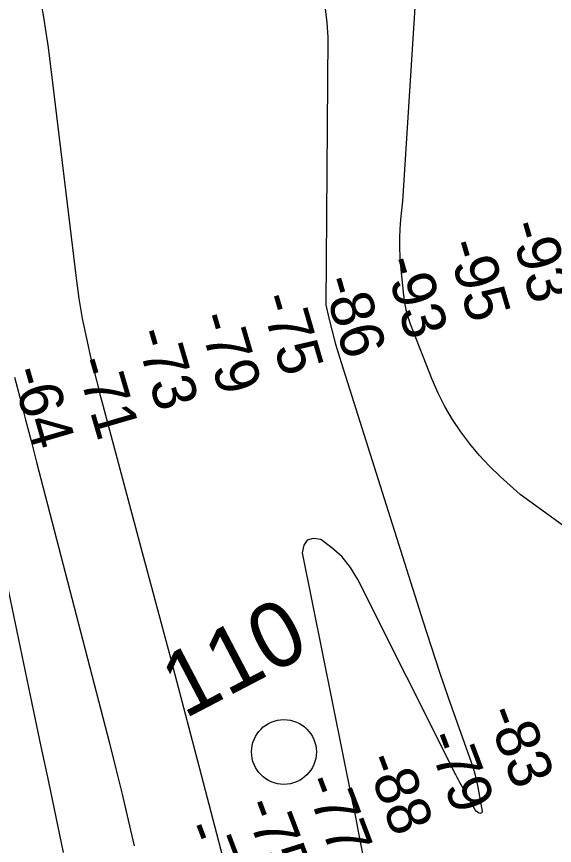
# Model space of a CAD drawing. Extents: x 3625074 to 3663148, y 511451 to 537151.
# Drawn here: x 3633034 to 3633863, y 523291 to 524570 of the extents above; entities that cross this region are included whole.
import ezdxf

# ---------------------------------------------------------------- set-up
doc = ezdxf.new("R2010")
doc.units = 0
for name, color, linetype in [('V-RIVR-IDEN', 7, 'Continuous'), ('V-RIVR-MILE', 7, 'Continuous'), ('V-RIVR-RANG', 7, 'Continuous'), ('V-TOPO-MAJR', 7, 'Continuous'), ('V-TOPO-MINR', 7, 'Continuous')]:
    doc.layers.add(name, color=color, linetype=linetype)

msp = doc.modelspace()

# ---------------------------------------------------------------- linework, layer by layer
at = {"layer": 'V-RIVR-MILE'}
msp.add_circle((3633445.9, 523435.4), 50, dxfattribs=at)
at = {"layer": 'V-TOPO-MAJR'}
msp.add_lwpolyline([(3632982.2, 523868.2), (3633060, 523498), (3633071.4, 523443.6), (3633082.8, 523389.3), (3633094.1, 523334.9), (3633105.4, 523280.5)], dxfattribs=at)
at = {"layer": 'V-TOPO-MINR'}
for points in [[(3634039.2, 523666.7), (3633809.9, 523832.9), (3633779.4, 523860.4), (3633762.8, 523876.4), (3633747, 523893.1), (3633732.3, 523910.9), (3633718.3, 523929.2), (3633705.7, 523948.5), (3633694, 523968.4), (3633683.8, 523989), (3633674.6, 524010.1), (3633641.2, 524095.5), (3633637.4, 524106.4), (3633634.3, 524117.4), (3633632, 524128.7), (3633630.5, 524140.2), (3633626.2, 524184.8), (3633625.2, 524199.1), (3633624.6, 524213.5), (3633624.7, 524227.9), (3633625.2, 524242.3), (3633626.3, 524256.7), (3633627.6, 524271.1), (3633629.4, 524285.4), (3633661.1, 524786.7)], [(3633493, 524716.3), (3633512.1, 524560.9), (3633513.6, 524538.2), (3633510.7, 524125.1), (3633515.1, 524104.7), (3633520, 524084.5), (3633525.5, 524064.4), (3633531.4, 524044.4), (3633659.9, 523637.6), (3633672.7, 523598.1), (3633685.7, 523558.6), (3633699.1, 523519.3), (3633712.9, 523480.1), (3633734.5, 523419.6), (3633737.4, 523410.7), (3633740, 523401.7), (3633742.3, 523392.6), (3633744.2, 523383.5), (3633751.5, 523344.2), (3633751.2, 523342.6), (3633750.6, 523341.4), (3633749.3, 523340.8), (3633747.7, 523340.6), (3633745.6, 523341.4), (3633742.1, 523344.1), (3633740.8, 523345.9), (3633719.3, 523384.5), (3633717.1, 523388.4), (3633715.1, 523392.3), (3633713, 523396.1), (3633711, 523400.1), (3633559.6, 523701.6), (3633548.4, 523719.8), (3633535.4, 523736.4), (3633519.9, 523750.6), (3633502.6, 523763.1), (3633490.7, 523764.6), (3633481.6, 523762.4), (3633476.4, 523754.5), (3633473.8, 523742.9), (3633551.8, 523356.8), (3633554, 523345.8), (3633556.2, 523334.8), (3633558.3, 523323.8), (3633560.5, 523312.8), (3633569.2, 523267.7)], [(3633071.1, 524592.4), (3633075.4, 524569.1), (3633079.1, 524545.6), (3633082.3, 524522.1), (3633089, 524467.6), (3633095.2, 524416.8), (3633101.4, 524365.9), (3633107.6, 524315.1), (3633113.7, 524264.2), (3633125.6, 524166.2), (3633130, 524135.1), (3633135.1, 524104.1), (3633141.4, 524073.3), (3633148.4, 524042.7), (3633160.9, 523992.7), (3633162.3, 523987.1), (3633163.7, 523981.6), (3633165.1, 523976.1), (3633166.6, 523970.6), (3633225.5, 523750.9), (3633247.5, 523668.7), (3633269.3, 523586.5), (3633291, 523504.2), (3633312.6, 523421.9), (3633353.8, 523264.4)], [(3633030.5, 524013.7), (3633039.1, 523980.9), (3633047.6, 523948.1), (3633056.1, 523915.3), (3633064.6, 523882.4), (3633176.8, 523449.1), (3633186.8, 523409.6), (3633196.6, 523370.1), (3633206, 523330.4), (3633215.2, 523290.8)]]:
    msp.add_lwpolyline(points, dxfattribs=at)

# ---------------------------------------------------------------- texts
at = {"layer": 'V-RIVR-IDEN'}
msp.add_text('110', height=100, rotation=27.6129, dxfattribs=at).set_placement((3633292.4, 523485.7))
at = {"layer": 'V-RIVR-RANG'}
for s, rotation, p in [('-93', 286.2525, (3633792.2, 524247.9)), ('-95', 286.2525, (3633696.5, 524218.6)), ('-93', 286.2525, (3633600, 524192.4)), ('-86', 286.2525, (3633504.5, 524162.6)), ('-75', 286.2525, (3633408.2, 524135.9)), ('-79', 286.2525, (3633312.6, 524106.3)), ('-73', 286.2525, (3633215.6, 524081.9)), ('-71', 286.2525, (3633124.3, 524037.7)), ('-64', 286.2525, (3633024.5, 524022.6)), ('-83', 290.7229, (3633756.3, 523495.8)), ('-79', 290.7229, (3633664.1, 523457)), ('-88', 290.7229, (3633570, 523423)), ('-77', 290.7229, (3633475.8, 523389.4)), ('-75', 290.7229, (3633382.6, 523353.2)), ('-70', 290.7229, (3633289.2, 523317.3))]:
    msp.add_text(s, height=67, rotation=rotation, dxfattribs=at).set_placement(p)

doc.saveas('drawing.dxf')
